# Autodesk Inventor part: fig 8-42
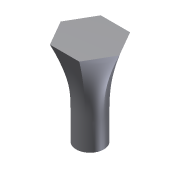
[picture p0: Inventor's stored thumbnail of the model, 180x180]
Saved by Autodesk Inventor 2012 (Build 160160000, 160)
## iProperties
Created: 2004-05
Part Number: fig 8-42
Document SubType Name: Modeling
Designer: CADCIM Technologies
Manufacturer: Standard
Standards Organization: Custom
Density: 1 g/cm^3
Material: Default
Author: CADCIM Technologies
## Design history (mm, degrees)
sketch "Sketch1"
  geometry: C1 r 16.344 at (0, 0)
  constraints: 1 centre point
extrude "Extrusion1" new body sketch "Sketch1" distance "d0" = 30.75; taper "d1" = 0 deg
workplane "Work Plane1"
sketch "Sketch2"
  geometry: L1 (34.788, 0)-(17.394, -30.128); L2 (17.394, -30.128)-(-17.394, -30.128); L3 (-17.394, -30.128)-(-34.788, 0); L4 (-34.788, 0)-(-17.394, 30.128); L5 (-17.394, 30.128)-(17.394, 30.128); L6 (17.394, 30.128)-(34.788, 0); 2 further points
  constraints: 12 end point, 1 coincident, 12 other
loft "Loft2" sketch "Sketch2" dims "d8" = 90 deg, "d11" = 10, "d12" = 0, "d13" = 90 deg
  node "Edges2"
body "Solid1"
other parameters: "d2" = 75
